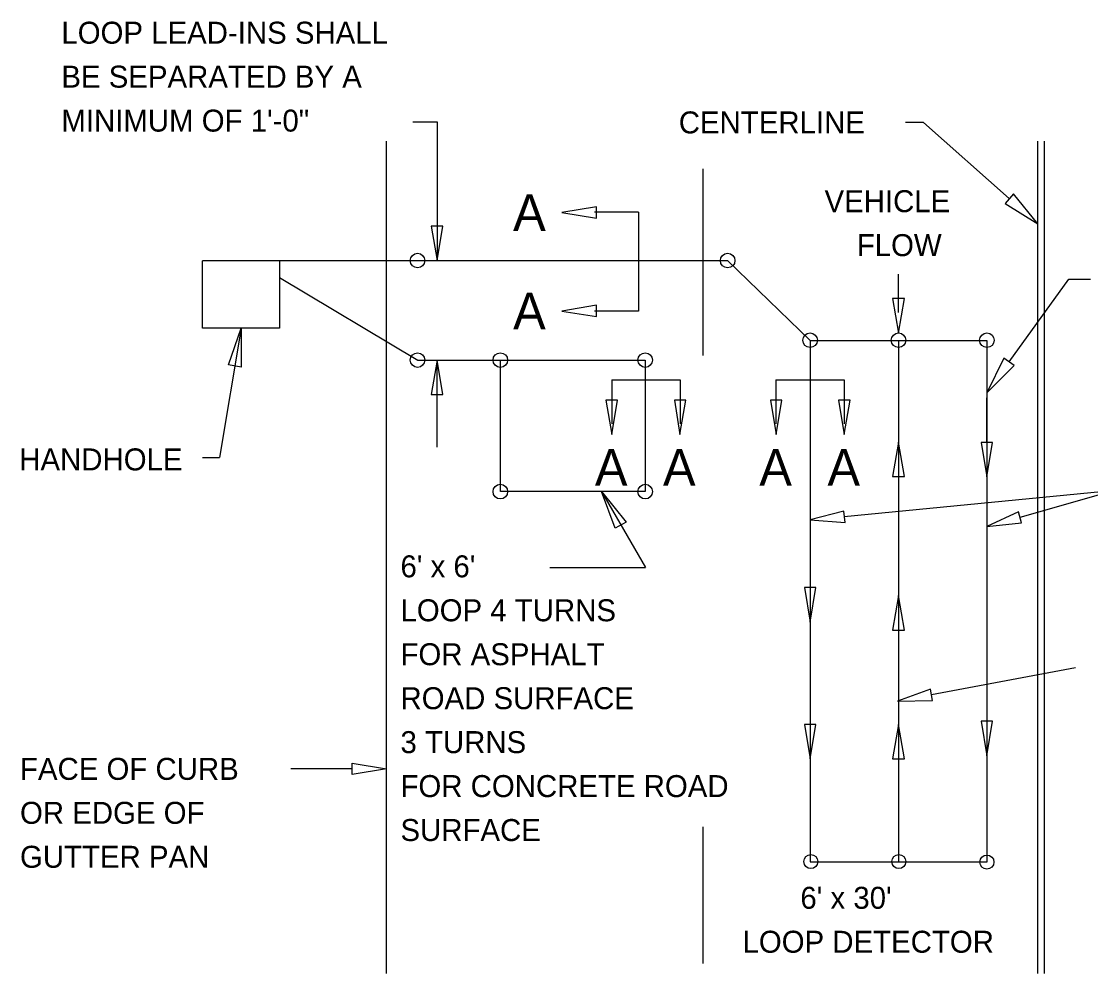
# Model space of a CAD drawing. Extents: x -1550.42 to -1543.2, y 2481.09 to 2491.
# Drawn here: x -1550.424 to -1547.504, y 2488.405 to 2491.005 of the extents above; entities that cross this region are included whole.
import ezdxf

# ---------------------------------------------------------------- set-up
doc = ezdxf.new("R2010")
doc.units = 0
for name, color, linetype in [('DETL-DIMS', 7, 'Continuous'), ('DETL-LINE', 7, 'Continuous'), ('DETL-NOTE', 7, 'Continuous')]:
    doc.layers.add(name, color=color, linetype=linetype)

msp = doc.modelspace()

# ---------------------------------------------------------------- linework, layer by layer
at = {"layer": 'DETL-DIMS'}
for p, q in [((-1549.355, 2490.731), (-1549.289, 2490.731)), ((-1549.289, 2490.731), (-1549.289, 2490.352)), ((-1547.961, 2490.729), (-1548.01, 2490.729)), ((-1547.727, 2490.521), (-1547.961, 2490.729)), ((-1548.029, 2490.21), (-1548.029, 2490.315)), ((-1547.727, 2490.075), (-1547.564, 2490.301)), ((-1547.564, 2490.301), (-1547.505, 2490.301)), ((-1549.824, 2490.167), (-1549.883, 2489.814)), ((-1549.289, 2489.842), (-1549.289, 2490.08)), ((-1549.93, 2489.814), (-1549.883, 2489.814)), ((-1548.177, 2489.653), (-1547.4373, 2489.7251)), ((-1547.697, 2489.651), (-1547.4373, 2489.7251)), ((-1548.84, 2489.721), (-1548.7202, 2489.5136)), ((-1548.9807, 2489.5136), (-1548.7202, 2489.5136)), ((-1547.939, 2489.167), (-1547.546, 2489.241)), ((-1549.521, 2488.964), (-1549.688, 2488.964))]:
    msp.add_line(p, q, dxfattribs=at)
for points in [[(-1547.715, 2490.534), (-1547.738, 2490.508), (-1547.649, 2490.452)], [(-1548.854, 2490.468), (-1548.854, 2490.499), (-1548.948, 2490.483)], [(-1549.273, 2490.446), (-1549.305, 2490.446), (-1549.289, 2490.352)], [(-1548.854, 2490.199), (-1548.854, 2490.23), (-1548.948, 2490.214)], [(-1548.013, 2490.248), (-1548.045, 2490.248), (-1548.029, 2490.154)], [(-1549.824, 2490.061), (-1549.859, 2490.067), (-1549.824, 2490.167)], [(-1549.305, 2489.986), (-1549.273, 2489.986), (-1549.289, 2490.08)], [(-1547.713, 2490.065), (-1547.741, 2490.085), (-1547.788, 2489.991)], [(-1548.796, 2489.971), (-1548.828, 2489.971), (-1548.812, 2489.877)], [(-1548.61, 2489.971), (-1548.641, 2489.971), (-1548.626, 2489.877)], [(-1548.348, 2489.971), (-1548.379, 2489.971), (-1548.363, 2489.877)], [(-1548.161, 2489.971), (-1548.193, 2489.971), (-1548.177, 2489.877)], [(-1548.045, 2489.762), (-1548.013, 2489.762), (-1548.029, 2489.856)], [(-1547.772, 2489.855), (-1547.803, 2489.855), (-1547.788, 2489.761)], [(-1548.773, 2489.638), (-1548.803, 2489.621), (-1548.84, 2489.721)], [(-1548.175, 2489.637), (-1548.178, 2489.668), (-1548.27, 2489.644)], [(-1547.693, 2489.636), (-1547.701, 2489.666), (-1547.788, 2489.626)], [(-1548.255, 2489.459), (-1548.286, 2489.459), (-1548.27, 2489.365)], [(-1548.045, 2489.343), (-1548.013, 2489.343), (-1548.029, 2489.437)], [(-1547.936, 2489.151), (-1547.942, 2489.182), (-1548.032, 2489.149)], [(-1548.255, 2489.085), (-1548.286, 2489.085), (-1548.27, 2488.991)], [(-1548.045, 2488.991), (-1548.013, 2488.991), (-1548.029, 2489.085)], [(-1547.772, 2489.094), (-1547.803, 2489.094), (-1547.788, 2489)], [(-1549.521, 2488.949), (-1549.521, 2488.98), (-1549.427, 2488.964)]]:
    msp.add_lwpolyline(points, close=True, dxfattribs=at)
for points in [[(-1548.739, 2490.484), (-1548.859, 2490.484)], [(-1548.739, 2490.484), (-1548.739, 2490.214)], [(-1548.739, 2490.214), (-1548.859, 2490.214)], [(-1548.812, 2490.026), (-1548.812, 2489.906)], [(-1548.812, 2490.026), (-1548.625, 2490.026)], [(-1548.625, 2490.026), (-1548.625, 2489.906)], [(-1548.364, 2490.026), (-1548.177, 2490.026)], [(-1548.364, 2490.026), (-1548.364, 2489.906)], [(-1548.177, 2490.026), (-1548.177, 2489.906)]]:
    msp.add_lwpolyline(points, dxfattribs=at)
at = {"layer": 'DETL-LINE'}
for p, q in [((-1549.427, 2488.405), (-1549.427, 2490.678)), ((-1547.649, 2488.405), (-1547.649, 2490.678)), ((-1547.63, 2488.405), (-1547.63, 2490.678)), ((-1548.563, 2490.602), (-1548.563, 2490.093)), ((-1549.93, 2490.352), (-1549.719, 2490.352)), ((-1549.93, 2490.167), (-1549.93, 2490.351)), ((-1549.719, 2490.352), (-1548.496, 2490.352)), ((-1549.719, 2490.352), (-1549.719, 2490.167)), ((-1548.496, 2490.352), (-1548.27, 2490.134)), ((-1549.719, 2490.306), (-1549.342, 2490.08)), ((-1549.719, 2490.167), (-1549.93, 2490.167)), ((-1548.27, 2490.134), (-1548.27, 2488.71)), ((-1548.27, 2490.134), (-1547.788, 2490.134)), ((-1548.029, 2490.134), (-1548.029, 2488.709)), ((-1547.788, 2490.134), (-1547.788, 2488.709)), ((-1549.342, 2490.08), (-1548.721, 2490.08)), ((-1549.116, 2489.721), (-1549.116, 2490.08)), ((-1548.721, 2490.08), (-1548.721, 2489.721)), ((-1547.788, 2489.855), (-1547.788, 2489.977)), ((-1548.721, 2489.721), (-1549.116, 2489.721)), ((-1548.563, 2488.806), (-1548.563, 2488.433)), ((-1547.788, 2488.709), (-1548.27, 2488.709))]:
    msp.add_line(p, q, dxfattribs=at)
for centre, radius in [((-1549.3425, 2490.3519), 0.0199), ((-1548.4956, 2490.3519), 0.0199), ((-1548.2704, 2490.1343), 0.0199), ((-1548.029, 2490.1343), 0.0199), ((-1547.7876, 2490.1343), 0.0199), ((-1549.3425, 2490.08), 0.0199), ((-1549.1164, 2490.08), 0.0199), ((-1548.7208, 2490.08), 0.0199), ((-1549.1164, 2489.721), 0.0199), ((-1548.7208, 2489.721), 0.0199), ((-1548.2684, 2488.7108), 0.0192), ((-1548.0281, 2488.7108), 0.0192), ((-1547.7876, 2488.7096), 0.0192)]:
    msp.add_circle(centre, radius, dxfattribs=at)
msp.add_arc((-1549.8922, 2490.3515), 0.000353, 90, 180, dxfattribs=at)

# ---------------------------------------------------------------- texts
at = {"layer": 'DETL-NOTE'}
for s, height, p in [('LOOP LEAD-INS SHALL', 0.06, (-1550.315, 2490.944)), ('BE SEPARATED BY A', 0.06, (-1550.315, 2490.824)), ('MINIMUM OF 1\'-0"', 0.06, (-1550.315, 2490.704)), ('CENTERLINE', 0.06, (-1548.629, 2490.699)), ('VEHICLE', 0.06, (-1548.231, 2490.484)), ('A', 0.1, (-1549.0815, 2490.433)), ('FLOW', 0.06, (-1548.143, 2490.364)), ('A', 0.1, (-1549.0815, 2490.164)), ('HANDHOLE', 0.06, (-1550.43, 2489.779)), ('A', 0.1, (-1548.8582, 2489.737)), ('A', 0.1, (-1548.6722, 2489.737)), ('A', 0.1, (-1548.4092, 2489.737)), ('A', 0.1, (-1548.2232, 2489.737)), ("6' x 6'", 0.06, (-1549.389, 2489.487)), ('LOOP 4 TURNS', 0.06, (-1549.389, 2489.367)), ('FOR ASPHALT', 0.06, (-1549.389, 2489.247)), ('ROAD SURFACE', 0.06, (-1549.389, 2489.127)), ('3 TURNS', 0.06, (-1549.389, 2489.007)), ('FACE OF CURB', 0.06, (-1550.428, 2488.934)), ('FOR CONCRETE ROAD', 0.06, (-1549.389, 2488.887)), ('OR EDGE OF', 0.06, (-1550.428, 2488.814)), ('SURFACE', 0.06, (-1549.389, 2488.767)), ('GUTTER PAN', 0.06, (-1550.428, 2488.694)), ("6' x 30'", 0.06, (-1548.297, 2488.582)), ('LOOP DETECTOR', 0.06, (-1548.455, 2488.462))]:
    msp.add_text(s, height=height, dxfattribs=at).set_placement(p)

doc.saveas('drawing.dxf')
